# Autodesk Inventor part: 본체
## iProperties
Created: 2015-01
Part Number: 본체
Document SubType Name: Modeling
Designer: elite
Density: 2.71 g/cm^3
Material: 알루미늄-6061
Mass: 1021.14 g
Surface Area: 1059.8 cm^2
Volume: 376.806 cm^3
Author: elite
